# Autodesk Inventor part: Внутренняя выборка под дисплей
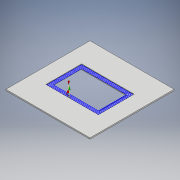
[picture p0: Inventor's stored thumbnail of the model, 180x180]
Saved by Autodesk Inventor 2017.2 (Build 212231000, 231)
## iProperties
Part Number: Внутренняя выборка под дисплей
Material: Типовые
Document SubType Name: Modeling
Designer: User
Density: 1 g/cm^3
Appearance: По умолчанию
Author: User
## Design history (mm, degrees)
sketch "Эскиз1"
  geometry: L1 (-100, -100)-(100, -100); L2 (100, -100)-(100, 100); L3 (100, 100)-(-100, 100); L4 (-100, 100)-(-100, -100); L5 (-100, -100)-(100, 100); L6 (100, -100)-(-100, 100); L7 (-54.5, -33)-(54.5, -33); L8 (54.5, -33)-(54.5, 33); L9 (54.5, 33)-(-54.5, 33); L10 (-54.5, 33)-(-54.5, -33); L11 (-54.5, -33)-(54.5, 33); L12 (54.5, -33)-(-54.5, 33); 1 further point
  constraints: 24 end point, 4 midpoint, 4 parallel, 2 horizontal, 2 perpendicular
  dimensions: "d0" = 200 distance of L3.end L2.end; "d1" = 200 distance of L2.end L1.end; "d2" = 109 distance of L9.end L8.end; "d3" = 66 distance of L8.end L7.end
extrude "Выдавливание1" new body sketch "Эскиз1" distance "d4" = 3; taper "d5" = 0 deg
sketch "Эскиз2"
  geometry: L1 (-62.5, -42.5)-(62.5, -42.5); L2 (62.5, -42.5)-(62.5, 42.5); L3 (62.5, 42.5)-(-62.5, 42.5); L4 (-62.5, 42.5)-(-62.5, -42.5); L5 (-62.5, -42.5)-(62.5, 42.5); L6 (62.5, -42.5)-(-62.5, 42.5); 1 further point
  constraints: 12 end point, 2 midpoint, 2 parallel, 1 horizontal, 1 perpendicular
  dimensions: "d6" = 125 distance of L3.end L2.end; "d7" = 85 distance of L2.end L1.end
extrude "Выдавливание2" cut sketch "Эскиз2" distance "d8" = 1.2; taper "d9" = 0 deg
node "Твердое тело1"
